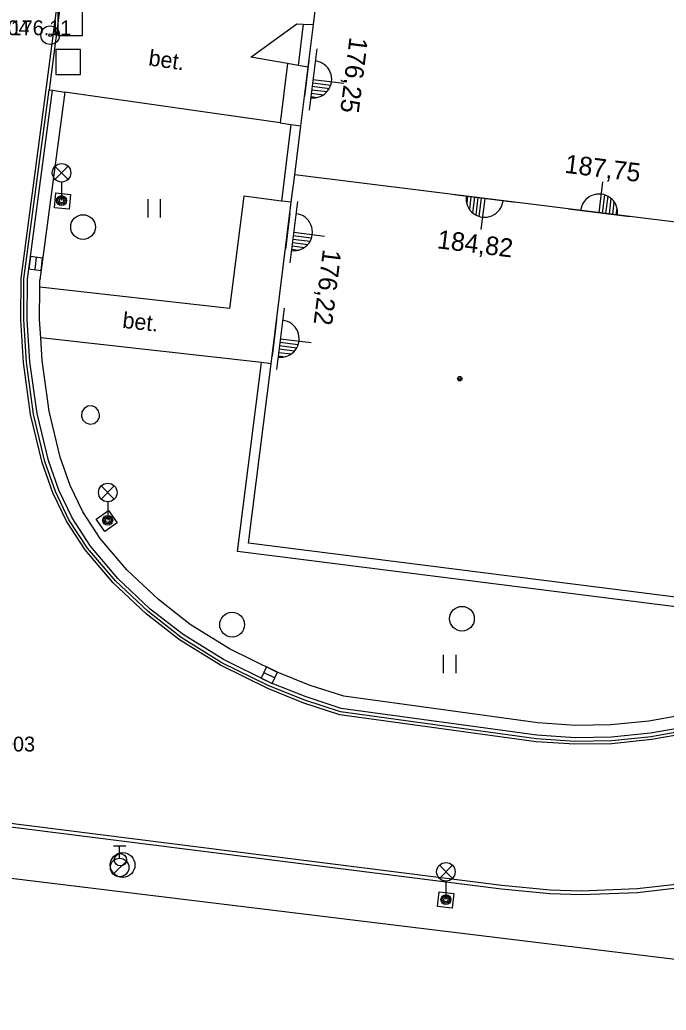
# Model space of a CAD drawing. Extents: x -540235 to -537963, y -1184915 to -1183660.
# Drawn here: x -540131 to -540104.85, y -1184067.19 to -1184027.14 of the extents above; entities that cross this region are included whole.
import ezdxf

# ---------------------------------------------------------------- set-up
doc = ezdxf.new("R2010")
doc.units = 0
for name, color, linetype in [('Vrstva 10', 7, 'Continuous'), ('Vrstva 11', 7, 'Continuous'), ('Vrstva 21', 7, 'Continuous'), ('Vrstva 22', 7, 'Continuous'), ('Vrstva 23', 7, 'Continuous'), ('Vrstva 26', 7, 'Continuous'), ('Vrstva 27', 7, 'Continuous'), ('Vrstva 28', 7, 'Continuous'), ('Vrstva 33', 7, 'Continuous'), ('Vrstva 36', 7, 'Continuous'), ('Vrstva 37', 7, 'Continuous'), ('Vrstva 39', 7, 'Continuous'), ('Vrstva 40', 7, 'Continuous'), ('Vrstva 5', 7, 'Continuous'), ('Vrstva 6', 7, 'Continuous'), ('Vrstva 7', 7, 'Continuous')]:
    doc.layers.add(name, color=color, linetype=linetype)

msp = doc.modelspace()

# ---------------------------------------------------------------- linework, layer by layer
at = {"layer": 'Vrstva 10'}
for p, q in [((-540130.83, -1184037.615), (-540129.817, -1184029.971)), ((-540130.442, -1184043.084), (-540130.73, -1184040.985)), ((-540110.1, -1184056.215), (-540118.03, -1184055.125)), ((-540111.5, -1184062.145), (-540140.41, -1184058.495)), ((-540104.32, -1184062.095), (-540106.023, -1184062.29))]:
    msp.add_line(p, q, dxfattribs=at)
for points in [[(-540130.73, -1184040.985), (-540130.837, -1184039.27), (-540130.83, -1184037.615)], [(-540125.812, -1184051.074), (-540127.13, -1184049.825), (-540128.256, -1184048.507), (-540129.01, -1184047.355), (-540129.553, -1184046.22), (-540129.98, -1184045.005), (-540130.442, -1184043.084)], [(-540118.03, -1184055.125), (-540119.465, -1184054.657), (-540120.92, -1184054.075), (-540122.825, -1184053.138), (-540124.47, -1184052.115), (-540125.812, -1184051.074)], [(-540096.764, -1184052.421), (-540097.399, -1184053.008), (-540098.45, -1184053.785), (-540099.625, -1184054.443), (-540101.05, -1184055.045), (-540102.454, -1184055.497), (-540104.05, -1184055.885), (-540105.458, -1184056.132)], [(-540105.458, -1184056.132), (-540107.05, -1184056.295), (-540108.537, -1184056.319), (-540110.1, -1184056.215)], [(-540106.023, -1184062.29), (-540108.29, -1184062.375), (-540109.548, -1184062.334), (-540111.5, -1184062.145)]]:
    msp.add_lwpolyline(points, dxfattribs=at)
at = {"layer": 'Vrstva 11'}
for p, q in [((-540129.936, -1184029.955), (-540129.419, -1184026.061)), ((-540129.3, -1184026.075), (-540129.817, -1184029.971)), ((-540119.535, -1184027.312), (-540119.732, -1184028.982)), ((-540120.17, -1184028.905), (-540120.47, -1184031.305)), ((-540130.95, -1184037.607), (-540129.936, -1184029.955)), ((-540130.689, -1184037.624), (-540129.677, -1184029.989)), ((-540129.182, -1184030.061), (-540130.189, -1184037.659)), ((-540120.47, -1184031.305), (-540129.182, -1184030.061)), ((-540120.031, -1184031.368), (-540120.41, -1184034.469)), ((-540122.52, -1184038.815), (-540130.19, -1184037.953)), ((-540121.219, -1184041.003), (-540130.149, -1184040)), ((-540130.56, -1184043.107), (-540130.849, -1184040.997)), ((-540130.303, -1184043.058), (-540130.589, -1184040.971)), ((-540129.811, -1184042.965), (-540130.092, -1184040.921)), ((-540122.19, -1184048.64), (-540121.219, -1184041.003)), ((-540120.833, -1184041.047), (-540121.219, -1184041.003)), ((-540102.35, -1184051.14), (-540122.19, -1184048.64)), ((-540110.035, -1184055.577), (-540117.886, -1184054.497)), ((-540110.086, -1184056.074), (-540117.998, -1184054.986)), ((-540110.112, -1184056.334), (-540118.057, -1184055.242)), ((-540105.442, -1184056.251), (-540107.043, -1184056.415)), ((-540111.517, -1184062.294), (-540140.429, -1184058.644)), ((-540104.297, -1184062.243), (-540106.012, -1184062.44))]:
    msp.add_line(p, q, dxfattribs=at)
for points in [[(-540119.333, -1184029.052), (-540119.732, -1184028.982), (-540120.17, -1184028.905), (-540121.65, -1184028.645), (-540119.79, -1184027.305), (-540119.535, -1184027.312), (-540119.117, -1184027.324)], [(-540129.817, -1184029.971), (-540129.677, -1184029.989), (-540129.182, -1184030.061)], [(-540120.47, -1184031.305), (-540120.031, -1184031.368), (-540119.63, -1184031.425)], [(-540129.601, -1184034.737), (-540129.54, -1184034.14), (-540128.943, -1184034.201), (-540129.004, -1184034.798), (-540129.601, -1184034.737)], [(-540120.017, -1184034.518), (-540120.41, -1184034.469), (-540121.94, -1184034.275), (-540122.52, -1184038.815)], [(-540130.849, -1184040.997), (-540130.958, -1184039.274), (-540130.95, -1184037.607)], [(-540130.589, -1184040.971), (-540130.696, -1184039.266), (-540130.689, -1184037.624)], [(-540130.092, -1184040.921), (-540130.149, -1184040), (-540130.196, -1184039.252), (-540130.19, -1184037.953), (-540130.189, -1184037.659)], [(-540125.394, -1184050.587), (-540126.664, -1184049.383), (-540127.742, -1184048.121), (-540128.45, -1184047.039), (-540128.96, -1184045.975), (-540129.364, -1184044.823), (-540129.811, -1184042.965)], [(-540127.77, -1184043.12), (-540127.809, -1184042.954), (-540127.919, -1184042.823), (-540128.076, -1184042.756), (-540128.247, -1184042.766), (-540128.395, -1184042.852), (-540128.488, -1184042.995), (-540128.507, -1184043.165), (-540128.448, -1184043.325), (-540128.323, -1184043.441), (-540128.159, -1184043.49), (-540127.991, -1184043.459), (-540127.855, -1184043.356), (-540127.779, -1184043.202), (-540127.77, -1184043.12)], [(-540125.891, -1184051.165), (-540127.217, -1184049.908), (-540128.352, -1184048.579), (-540129.115, -1184047.414), (-540129.664, -1184046.266), (-540130.095, -1184045.039), (-540130.56, -1184043.107)], [(-540125.72, -1184050.967), (-540127.027, -1184049.727), (-540128.143, -1184048.422), (-540128.887, -1184047.285), (-540129.422, -1184046.166), (-540129.844, -1184044.965), (-540130.303, -1184043.058)], [(-540127.413, -1184046.989), (-540127.066, -1184047.479), (-540127.556, -1184047.826), (-540127.903, -1184047.336), (-540127.413, -1184046.989)], [(-540117.886, -1184054.497), (-540119.247, -1184054.054), (-540120.659, -1184053.489), (-540122.513, -1184052.576), (-540124.103, -1184051.588), (-540125.394, -1184050.587)], [(-540117.998, -1184054.986), (-540119.417, -1184054.524), (-540120.862, -1184053.946), (-540122.756, -1184053.014), (-540124.389, -1184051.999), (-540125.72, -1184050.967)], [(-540118.057, -1184055.242), (-540119.506, -1184054.77), (-540120.969, -1184054.185), (-540122.883, -1184053.243), (-540124.539, -1184052.213), (-540125.891, -1184051.165)], [(-540097.322, -1184053.101), (-540098.385, -1184053.886), (-540099.572, -1184054.551), (-540101.008, -1184055.157), (-540102.421, -1184055.613), (-540104.025, -1184056.002), (-540105.442, -1184056.251)], [(-540101.099, -1184054.912), (-540102.492, -1184055.361), (-540104.079, -1184055.746), (-540105.477, -1184055.992), (-540107.058, -1184056.154), (-540108.533, -1184056.177), (-540110.086, -1184056.074)], [(-540102.628, -1184054.88), (-540104.181, -1184055.257), (-540105.546, -1184055.497), (-540107.088, -1184055.654), (-540108.52, -1184055.677), (-540110.035, -1184055.577)], [(-540107.043, -1184056.415), (-540108.54, -1184056.439), (-540110.112, -1184056.334)], [(-540114.105, -1184062.996), (-540114.036, -1184062.4), (-540113.44, -1184062.47), (-540113.51, -1184063.066), (-540114.105, -1184062.996)], [(-540106.012, -1184062.44), (-540108.29, -1184062.525), (-540109.558, -1184062.483), (-540111.517, -1184062.294)]]:
    msp.add_lwpolyline(points, dxfattribs=at)
at = {"layer": 'Vrstva 21'}
for radius in [0.375, 0.05]:
    msp.add_circle((-540129.77, -1184027.76), radius, dxfattribs=at)
at = {"layer": 'Vrstva 26'}
for points in [[(-540129.46, -1184027.775), (-540128.46, -1184027.775), (-540128.46, -1184026.775), (-540129.46, -1184026.775)], [(-540129.54, -1184029.345), (-540128.54, -1184029.345), (-540128.54, -1184028.345), (-540129.54, -1184028.345)]]:
    msp.add_lwpolyline(points, close=True, dxfattribs=at)
at = {"layer": 'Vrstva 27'}
for p, q in [((-540130.383, -1184037.243), (-540130.323, -1184036.747)), ((-540121.132, -1184053.537), (-540120.68, -1184053.753))]:
    msp.add_line(p, q, dxfattribs=at)
for points in [[(-540130.135, -1184037.273), (-540130.075, -1184036.777), (-540130.571, -1184036.717), (-540130.631, -1184037.213)], [(-540121.239, -1184053.763), (-540120.788, -1184053.978), (-540120.573, -1184053.527), (-540121.024, -1184053.312)]]:
    msp.add_lwpolyline(points, close=True, dxfattribs=at)
for centre in [(-540128.44, -1184035.52), (-540113.11, -1184051.36), (-540122.41, -1184051.6), (-540126.84, -1184061.32)]:
    msp.add_circle(centre, 0.5, dxfattribs=at)
at = {"layer": 'Vrstva 28'}
for p, q in [((-540127.21, -1184060.545), (-540126.71, -1184060.545)), ((-540126.96, -1184061.045), (-540126.96, -1184060.545)), ((-540127.218, -1184061.692), (-540126.688, -1184061.162))]:
    msp.add_line(p, q, dxfattribs=at)
for centre, radius in [((-540126.96, -1184061.42), 0.375), ((-540126.93, -1184061.11), 0.25)]:
    msp.add_circle(centre, radius, dxfattribs=at)
at = {"layer": 'Vrstva 33'}
for p, q in [((-540129.575, -1184033.59), (-540129.045, -1184033.06)), ((-540129.575, -1184033.06), (-540129.045, -1184033.59)), ((-540129.31, -1184033.7), (-540129.31, -1184034.45)), ((-540127.705, -1184046.52), (-540127.175, -1184045.99)), ((-540127.705, -1184045.99), (-540127.175, -1184046.52)), ((-540127.44, -1184046.63), (-540127.44, -1184047.38)), ((-540114.025, -1184061.86), (-540113.495, -1184061.33)), ((-540114.025, -1184061.33), (-540113.495, -1184061.86)), ((-540113.76, -1184061.97), (-540113.76, -1184062.72))]:
    msp.add_line(p, q, dxfattribs=at)
for centre, radius in [((-540129.31, -1184033.325), 0.375), ((-540129.31, -1184034.45), 0.2), ((-540129.31, -1184034.45), 0.1445), ((-540129.31, -1184034.45), 0.0876), ((-540127.44, -1184046.255), 0.375), ((-540127.44, -1184047.38), 0.2), ((-540127.44, -1184047.38), 0.1445), ((-540127.44, -1184047.38), 0.0876), ((-540113.76, -1184061.595), 0.375), ((-540113.76, -1184062.72), 0.2), ((-540113.76, -1184062.72), 0.1445), ((-540113.76, -1184062.72), 0.0876)]:
    msp.add_circle(centre, radius, dxfattribs=at)
at = {"layer": 'Vrstva 36'}
for p, q in [((-540125.805, -1184035.138), (-540125.805, -1184034.388)), ((-540125.305, -1184035.138), (-540125.305, -1184034.388)), ((-540113.851, -1184053.566), (-540113.851, -1184052.816)), ((-540113.351, -1184053.566), (-540113.351, -1184052.816))]:
    msp.add_line(p, q, dxfattribs=at)
at = {"layer": 'Vrstva 37'}
for p, q in [((-540118.983, -1184028.307), (-540119.295, -1184030.787)), ((-540119.174, -1184029.825), (-540118.475, -1184029.912)), ((-540119.156, -1184029.686), (-540118.417, -1184029.779)), ((-540119.139, -1184029.547), (-540117.891, -1184029.704)), ((-540119.209, -1184030.103), (-540118.706, -1184030.166)), ((-540119.191, -1184029.964), (-540118.566, -1184030.042)), ((-540119.226, -1184030.242), (-540118.95, -1184030.276)), ((-540107.564, -1184034.941), (-540107.409, -1184033.693)), ((-540110.95, -1184034.52), (-540113.43, -1184034.212)), ((-540107.425, -1184034.958), (-540107.333, -1184034.219)), ((-540119.76, -1184034.485), (-540120.072, -1184036.965)), ((-540112.885, -1184034.28), (-540112.919, -1184034.556)), ((-540112.746, -1184034.297), (-540112.808, -1184034.8)), ((-540112.607, -1184034.314), (-540112.685, -1184034.939)), ((-540112.468, -1184034.331), (-540112.555, -1184035.03)), ((-540112.329, -1184034.349), (-540112.421, -1184035.088)), ((-540112.19, -1184034.366), (-540112.345, -1184035.614)), ((-540107.286, -1184034.976), (-540107.199, -1184034.277)), ((-540107.147, -1184034.993), (-540107.069, -1184034.368)), ((-540107.008, -1184035.01), (-540106.946, -1184034.507)), ((-540108.804, -1184034.787), (-540106.324, -1184035.095)), ((-540106.869, -1184035.027), (-540106.835, -1184034.752)), ((-540119.916, -1184035.725), (-540118.668, -1184035.882)), ((-540119.968, -1184036.142), (-540119.343, -1184036.22)), ((-540119.951, -1184036.003), (-540119.252, -1184036.09)), ((-540119.933, -1184035.864), (-540119.194, -1184035.957)), ((-540120.003, -1184036.42), (-540119.727, -1184036.454)), ((-540119.986, -1184036.281), (-540119.483, -1184036.344)), ((-540120.299, -1184038.794), (-540120.611, -1184041.274)), ((-540120.472, -1184040.173), (-540119.733, -1184040.266)), ((-540120.455, -1184040.034), (-540119.207, -1184040.191)), ((-540120.525, -1184040.59), (-540120.022, -1184040.653)), ((-540120.507, -1184040.451), (-540119.882, -1184040.529)), ((-540120.49, -1184040.312), (-540119.791, -1184040.399)), ((-540120.542, -1184040.729), (-540120.266, -1184040.763))]:
    msp.add_line(p, q, dxfattribs=at)
for centre, start, end in [((-540119.1309, -1184029.548), 262.22271, 83.46875), ((-540107.563, -1184034.9329), 352.28535, 173.53139), ((-540112.191, -1184034.3741), 172.29048, 353.53653), ((-540119.9079, -1184035.726), 262.22271, 83.46875), ((-540120.4469, -1184040.035), 262.22271, 83.46875)]:
    msp.add_arc(centre, 0.75, start, end, dxfattribs=at)
at = {"layer": 'Vrstva 39'}
for radius in [0.09, 0.0398]:
    msp.add_circle((-540113.199, -1184041.653), radius, dxfattribs=at)
at = {"layer": 'Vrstva 5'}
for p, q in [((-540119.117, -1184027.324), (-540118.952, -1184026.008)), ((-540119.333, -1184029.052), (-540119.117, -1184027.324)), ((-540119.63, -1184031.425), (-540119.333, -1184029.052)), ((-540119.878, -1184033.41), (-540119.63, -1184031.425)), ((-540120.017, -1184034.518), (-540119.878, -1184033.41)), ((-540100.828, -1184035.779), (-540119.878, -1184033.41)), ((-540120.833, -1184041.047), (-540120.017, -1184034.518)), ((-540121.74, -1184048.3), (-540120.833, -1184041.047)), ((-540102.71, -1184050.71), (-540121.74, -1184048.3))]:
    msp.add_line(p, q, dxfattribs=at)
at = {"layer": 'Vrstva 6'}
for p, q in [((-540119.3, -1184028.79), (-540119.482, -1184030.24)), ((-540120.072, -1184034.959), (-540120.255, -1184036.428)), ((-540120.611, -1184039.269), (-540120.794, -1184040.737))]:
    msp.add_line(p, q, dxfattribs=at)
at = {"layer": 'Vrstva 7'}
msp.add_line((-540087.769, -1184067.192), (-540140.75, -1184060.715), dxfattribs=at)

# ---------------------------------------------------------------- texts
at = {"layer": 'Vrstva 22'}
msp.add_text('176.11', height=0.6, dxfattribs=at).set_placement((-540131.37, -1184027.76))
at = {"layer": 'Vrstva 23'}
for s, p in [('4004 ', (-540132.387, -1184027.76)), (' 4003', (-540132.39, -1184056.73))]:
    msp.add_text(s, height=0.6, dxfattribs=at).set_placement(p)
at = {"layer": 'Vrstva 37'}
for s, rotation, p in [('176,25', 262.82978, (-540117.654, -1184027.814)), ('187,75', 352.91198, (-540108.978, -1184033.322)), ('184,82', 352.91198, (-540114.142, -1184036.375)), ('176,22', 262.82978, (-540118.731, -1184036.394))]:
    msp.add_text(s, height=0.75, rotation=rotation, dxfattribs=at).set_placement(p)
at = {"layer": 'Vrstva 40'}
for rotation, p in [(351.87772, (-540125.819, -1184028.979)), (353.5919, (-540126.869, -1184039.594))]:
    msp.add_text('bet.', height=0.65, rotation=rotation, dxfattribs=at).set_placement(p)

doc.saveas('drawing.dxf')
